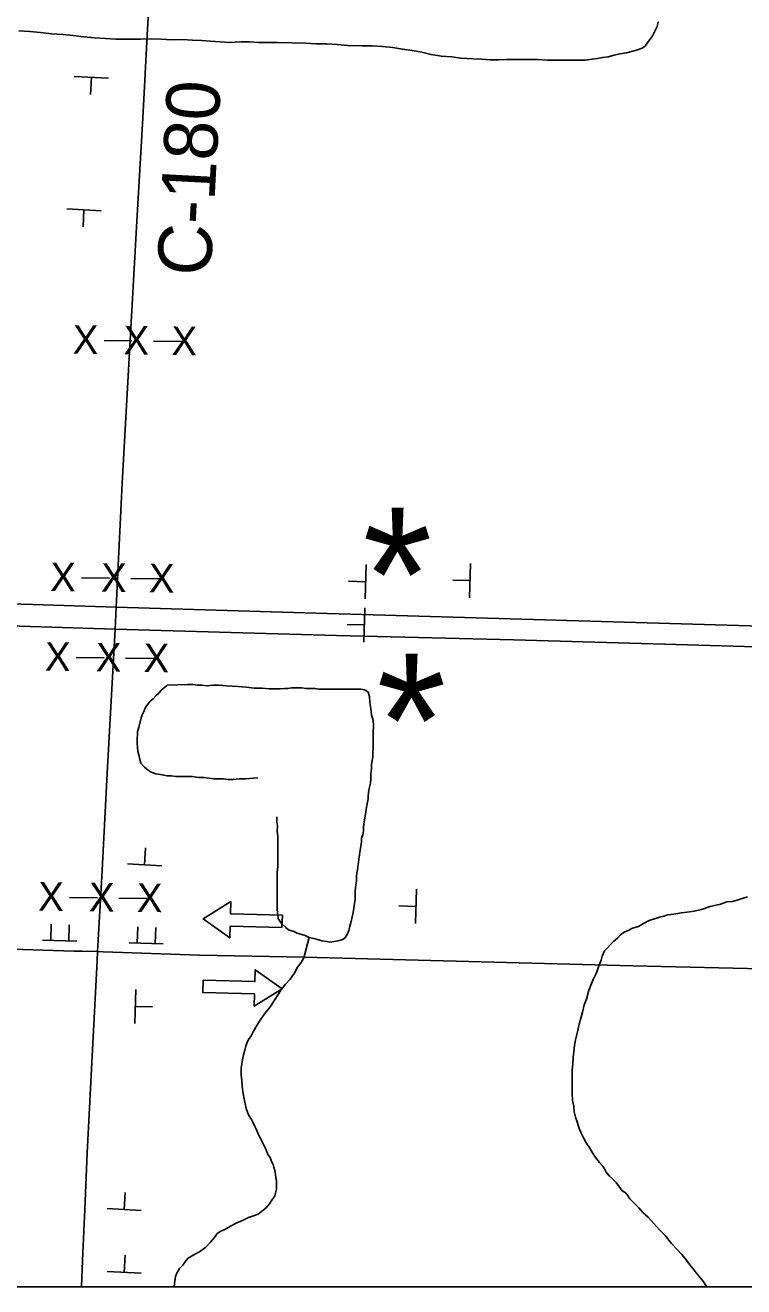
# Model space of a CAD drawing. Extents: x 1 to 1675, y -2 to 1113.
# Drawn here: x 1656.23 to 1659.58, y 1085.8 to 1091.69 of the extents above; entities that cross this region are included whole.
import ezdxf

# ---------------------------------------------------------------- set-up
doc = ezdxf.new("R2010")
doc.units = 0
for name, color, linetype in [('GM_X_County_Road_Text', 7, 'Continuous'), ('GM_X_State_Route', 7, 'Continuous'), ('SC_Scratch1', 7, 'Continuous'), ('SH_Data', 7, 'Continuous'), ('SH_Text', 7, 'Continuous'), ('SN_P_Signs', 7, 'Continuous'), ('SN_P_Text', 7, 'Continuous'), ('SN_X_Public', 7, 'Continuous')]:
    doc.layers.add(name, color=color, linetype=linetype)

msp = doc.modelspace()

# ---------------------------------------------------------------- linework, layer by layer
at = {"layer": 'GM_X_State_Route'}
for points in [[(1653.1763, 1089.0716), (1653.7087, 1089.0563), (1654.4064, 1089.0358), (1654.8887, 1089.0196), (1655.371, 1089.0075), (1656.2656, 1088.9829), (1656.6538, 1088.9713), (1657.5335, 1088.9451), (1659.6102, 1088.8844), (1660.288, 1088.8659), (1660.8126, 1088.8494), (1661.4466, 1088.8312), (1662.4959, 1088.8007), (1663.3048, 1088.777), (1663.7714, 1088.7638), (1663.8294, 1088.7624), (1664.6819, 1088.737), (1665.1629, 1088.7239), (1665.8187, 1088.7038), (1666.2558, 1088.6901), (1667.4561, 1088.6514), (1667.5998, 1088.6492), (1667.8763, 1088.6439)], [(1653.1763, 1089.0716), (1653.7087, 1089.0563), (1654.4064, 1089.0358), (1654.8887, 1089.0196), (1655.371, 1089.0075), (1656.2656, 1088.9829), (1656.6538, 1088.9713), (1657.5335, 1088.9451), (1659.6102, 1088.8844)], [(1653.1763, 1088.972), (1654.1058, 1088.9448), (1655.1549, 1088.9137), (1655.8542, 1088.8935), (1656.6489, 1088.8688), (1657.2445, 1088.8506), (1657.6825, 1088.8393), (1658.51, 1088.8187), (1659.3192, 1088.7948), (1660.9157, 1088.748), (1661.55, 1088.7295), (1662.0093, 1088.7178), (1663.1466, 1088.6833), (1663.7686, 1088.6652), (1664.4369, 1088.6454), (1665.8366, 1088.6041), (1666.8645, 1088.5732), (1667.7577, 1088.5488), (1667.8763, 1088.5445)], [(1653.1763, 1088.972), (1654.1058, 1088.9448), (1655.1549, 1088.9137), (1655.8542, 1088.8935), (1656.6489, 1088.8688), (1657.2445, 1088.8506), (1657.6825, 1088.8393), (1658.51, 1088.8187), (1659.3192, 1088.7948), (1660.9157, 1088.748), (1661.55, 1088.7295), (1662.0093, 1088.7178), (1663.1466, 1088.6833), (1663.7686, 1088.6652), (1664.4369, 1088.6454), (1665.8366, 1088.6041), (1666.8645, 1088.5732), (1667.7577, 1088.5488), (1668.0608, 1088.5378), (1669.2047, 1088.5077), (1669.5547, 1088.5002), (1670.1889, 1088.4798), (1670.4622, 1088.472)]]:
    msp.add_lwpolyline(points, dxfattribs=at)
at = {"layer": 'SC_Scratch1'}
for points in [[(1659.1832, 1091.7008), (1659.1778, 1091.6794), (1659.1671, 1091.658), (1659.1563, 1091.6367), (1659.1456, 1091.6206), (1659.1349, 1091.6073), (1659.1214, 1091.5886), (1659.108, 1091.5779), (1659.0813, 1091.57), (1659.0652, 1091.5647), (1659.0357, 1091.5568), (1659.0036, 1091.5515), (1658.9769, 1091.5463), (1658.9501, 1091.5383), (1658.9233, 1091.5357), (1658.8992, 1091.5305), (1658.8751, 1091.5279), (1658.843, 1091.5226), (1658.8082, 1091.5227), (1658.752, 1091.5229), (1658.7092, 1091.5231), (1658.6664, 1091.5232), (1658.6209, 1091.526), (1658.5835, 1091.5261), (1658.546, 1091.5262), (1658.5112, 1091.5263), (1658.4738, 1091.5265), (1658.439, 1091.5239), (1658.3988, 1091.524), (1658.3587, 1091.5268), (1658.3186, 1091.5296)], [(1658.3186, 1091.5296), (1658.2624, 1091.5325), (1658.2196, 1091.538), (1658.1714, 1091.5408), (1658.1233, 1091.549), (1658.0805, 1091.5598), (1658.035, 1091.568), (1657.9896, 1091.5735), (1657.9441, 1091.5817), (1657.8959, 1091.5872), (1657.8478, 1091.59), (1657.7996, 1091.5901), (1657.7354, 1091.5904), (1657.6846, 1091.5959), (1657.6364, 1091.5987), (1657.5856, 1091.5989), (1657.5374, 1091.6017), (1657.4063, 1091.6048), (1657.3635, 1091.6049), (1657.318, 1091.6051), (1657.2779, 1091.6079), (1657.2377, 1091.608), (1657.1815, 1091.6055), (1657.1387, 1091.6083), (1657.0933, 1091.6111), (1657.0531, 1091.6139), (1657.0103, 1091.6167), (1656.9622, 1091.6196), (1656.9113, 1091.6171), (1656.8632, 1091.6199), (1656.8177, 1091.6227), (1656.7695, 1091.6202), (1656.7187, 1091.6203), (1656.6518, 1091.6206), (1656.6036, 1091.6234), (1656.5528, 1091.6262), (1656.502, 1091.6317), (1656.4538, 1091.6372), (1656.4057, 1091.6428), (1656.3521, 1091.6456), (1656.3013, 1091.6511), (1656.2505, 1091.6566), (1656.1997, 1091.6595)], [(1656.8922, 1088.6067), (1656.8884, 1088.6046), (1656.8642, 1088.5832), (1656.8535, 1088.5699), (1656.8401, 1088.5592), (1656.8267, 1088.5432), (1656.8133, 1088.5326), (1656.7918, 1088.5059), (1656.7811, 1088.4818), (1656.7757, 1088.4685), (1656.7703, 1088.4551), (1656.7595, 1088.4097), (1656.7541, 1088.391), (1656.7541, 1088.3776), (1656.7513, 1088.3589), (1656.7513, 1088.3375), (1656.7539, 1088.3134), (1656.7565, 1088.292), (1656.7619, 1088.2759), (1656.7645, 1088.2598), (1656.7698, 1088.2437), (1656.7858, 1088.225), (1656.7992, 1088.2142), (1656.8179, 1088.2008), (1656.8393, 1088.1927), (1656.8607, 1088.19), (1656.8767, 1088.1872), (1656.8901, 1088.1845), (1656.9115, 1088.1845), (1656.9329, 1088.1817), (1656.957, 1088.1816), (1656.9811, 1088.1815), (1657.0078, 1088.1815), (1657.0399, 1088.176), (1657.0667, 1088.1759), (1657.0881, 1088.1732), (1657.1095, 1088.1704), (1657.1335, 1088.1704), (1657.155, 1088.1703), (1657.1763, 1088.1675), (1657.2004, 1088.1675), (1657.2272, 1088.1701), (1657.2593, 1088.1699), (1657.2941, 1088.1725), (1657.3151, 1088.174)], [(1657.7071, 1087.4194), (1657.7205, 1087.4274), (1657.7313, 1087.4434), (1657.7393, 1087.4621), (1657.7447, 1087.4835), (1657.7501, 1087.5049), (1657.7555, 1087.5263), (1657.7582, 1087.5396), (1657.7609, 1087.5557), (1657.7664, 1087.5878), (1657.7691, 1087.6092), (1657.7691, 1087.6279), (1657.7692, 1087.6493), (1657.7719, 1087.6734), (1657.7746, 1087.6948), (1657.7747, 1087.7135), (1657.7774, 1087.7322), (1657.7801, 1087.7456), (1657.7828, 1087.7697), (1657.791, 1087.8285), (1657.7937, 1087.8472), (1657.7964, 1087.8632), (1657.7991, 1087.8793), (1657.7992, 1087.8927), (1657.8045, 1087.9087), (1657.8073, 1087.9274), (1657.8073, 1087.9435), (1657.81, 1087.9595), (1657.8127, 1087.9782), (1657.8181, 1088.005), (1657.8209, 1088.0264), (1657.8236, 1088.0451), (1657.8263, 1088.0611), (1657.829, 1088.0772), (1657.8291, 1088.0906), (1657.8318, 1088.1066), (1657.8345, 1088.1253), (1657.8399, 1088.1494), (1657.8426, 1088.1708), (1657.8427, 1088.1922), (1657.8454, 1088.2162), (1657.8454, 1088.2377), (1657.8482, 1088.2537), (1657.8509, 1088.2724), (1657.8509, 1088.2938), (1657.8537, 1088.3152), (1657.8537, 1088.3366), (1657.8537, 1088.3553), (1657.8538, 1088.3741), (1657.8538, 1088.3928), (1657.8539, 1088.4089), (1657.8539, 1088.4249), (1657.8513, 1088.449), (1657.846, 1088.4677), (1657.8433, 1088.4865), (1657.8407, 1088.5079), (1657.8381, 1088.5266), (1657.8355, 1088.5534), (1657.8302, 1088.5748), (1657.8141, 1088.5856), (1657.7954, 1088.5883), (1657.774, 1088.5884), (1657.7606, 1088.5884), (1657.7446, 1088.5885), (1657.7205, 1088.5885), (1657.7044, 1088.5886), (1657.6911, 1088.5886), (1657.675, 1088.5887), (1657.6616, 1088.5887), (1657.6482, 1088.5888), (1657.6322, 1088.5888), (1657.6161, 1088.5889), (1657.6001, 1088.5889), (1657.5813, 1088.5917), (1657.5626, 1088.5917), (1657.5412, 1088.5918), (1657.5198, 1088.5945), (1657.4904, 1088.5946), (1657.4717, 1088.5947), (1657.4556, 1088.5921), (1657.4395, 1088.5921), (1657.4208, 1088.5895), (1657.3967, 1088.5896), (1657.3673, 1088.5897), (1657.3352, 1088.5924), (1657.2977, 1088.5925), (1657.2603, 1088.598), (1657.2228, 1088.6008), (1657.1693, 1088.6037), (1657.1345, 1088.6065), (1657.1051, 1088.6065), (1657.0783, 1088.604), (1657.0543, 1088.6067), (1657.0329, 1088.6068), (1657.0115, 1088.6095), (1656.9874, 1088.6096), (1656.8922, 1088.6067)], [(1657.4034, 1087.9934), (1657.4034, 1087.9822), (1657.4033, 1087.9688), (1657.406, 1087.9501), (1657.4059, 1087.926), (1657.4085, 1087.9019), (1657.4085, 1087.8779), (1657.4084, 1087.8591), (1657.4084, 1087.8431), (1657.4083, 1087.8217), (1657.4083, 1087.8029), (1657.4083, 1087.7842), (1657.4082, 1087.7601), (1657.4055, 1087.7361), (1657.4054, 1087.712), (1657.4054, 1087.6879), (1657.4053, 1087.6692), (1657.4053, 1087.6505), (1657.4052, 1087.6291), (1657.4052, 1087.613), (1657.4051, 1087.5969), (1657.4051, 1087.5782), (1657.4051, 1087.5595), (1657.4077, 1087.5354), (1657.4103, 1087.5193), (1657.4183, 1087.5059), (1657.429, 1087.4925), (1657.445, 1087.4764), (1657.4584, 1087.4657), (1657.4824, 1087.4576), (1657.4985, 1087.4495), (1657.5199, 1087.4441), (1657.5359, 1087.4387), (1657.5546, 1087.4306), (1657.576, 1087.4252), (1657.6001, 1087.4197), (1657.6135, 1087.4143), (1657.6375, 1087.4116), (1657.6509, 1087.4089), (1657.6696, 1087.4115), (1657.6884, 1087.4141), (1657.7071, 1087.4194)], [(1659.5993, 1087.6194), (1659.5752, 1087.6114), (1659.5511, 1087.6035), (1659.5297, 1087.5982), (1659.5029, 1087.5956), (1659.4735, 1087.585), (1659.4253, 1087.5745), (1659.3851, 1087.5612), (1659.3503, 1087.5533), (1659.3182, 1087.548), (1659.2914, 1087.5455), (1659.2647, 1087.5402), (1659.2433, 1087.5376), (1659.2272, 1087.5349), (1659.2085, 1087.5297), (1659.1897, 1087.5244), (1659.171, 1087.5191), (1659.1415, 1087.5085), (1659.1147, 1087.4952), (1659.0906, 1087.4819), (1659.0638, 1087.4739), (1659.0424, 1087.4633), (1659.0237, 1087.4553), (1659.0076, 1087.442), (1658.9942, 1087.4287), (1658.9754, 1087.4127), (1658.9325, 1087.3673), (1658.9217, 1087.3433), (1658.9163, 1087.3246), (1658.9056, 1087.2979), (1658.8948, 1087.2658), (1658.8813, 1087.2364), (1658.8679, 1087.207), (1658.8571, 1087.1776), (1658.849, 1087.1429), (1658.8383, 1087.1161), (1658.8301, 1087.0814), (1658.814, 1087.0253), (1658.8059, 1086.9905), (1658.7977, 1086.9531), (1658.7923, 1086.9263), (1658.7896, 1086.8969), (1658.7868, 1086.8702), (1658.7841, 1086.8407), (1658.7814, 1086.8113), (1658.7813, 1086.7739), (1658.7812, 1086.7391), (1658.7811, 1086.7043), (1658.7837, 1086.6695), (1658.789, 1086.6427), (1658.7916, 1086.616), (1658.7969, 1086.5919), (1658.8049, 1086.5705), (1658.8129, 1086.5437), (1658.8235, 1086.5169), (1658.8341, 1086.4955), (1658.8475, 1086.4713), (1658.8635, 1086.4472), (1658.8768, 1086.4257), (1658.8901, 1086.4043), (1658.9088, 1086.3802), (1658.9222, 1086.3667), (1658.9302, 1086.3533), (1658.9408, 1086.3346), (1658.9542, 1086.3185)], [(1657.5546, 1087.4306), (1657.5303, 1087.3344), (1657.5169, 1087.313), (1657.5008, 1087.2916), (1657.4847, 1087.2623), (1657.4659, 1087.2356), (1657.4444, 1087.2116), (1657.4229, 1087.1849), (1657.4095, 1087.1635), (1657.3934, 1087.1368), (1657.3746, 1087.1074), (1657.3478, 1087.0754), (1657.329, 1087.0487), (1657.3102, 1087.0193), (1657.2941, 1086.9926), (1657.2833, 1086.9713), (1657.2726, 1086.9553), (1657.2645, 1086.9419), (1657.2591, 1086.9232), (1657.2537, 1086.9045), (1657.2483, 1086.8831), (1657.2429, 1086.859), (1657.2402, 1086.8403), (1657.2375, 1086.8216), (1657.2374, 1086.8055), (1657.2374, 1086.7868), (1657.24, 1086.7627), (1657.2426, 1086.736), (1657.2453, 1086.7092), (1657.2505, 1086.6771), (1657.2611, 1086.6316), (1657.2718, 1086.6021), (1657.2851, 1086.5807), (1657.2931, 1086.5646), (1657.3011, 1086.5485), (1657.3091, 1086.5324), (1657.3171, 1086.5137), (1657.3277, 1086.4922), (1657.3384, 1086.4708), (1657.3463, 1086.4547), (1657.3543, 1086.4386), (1657.3623, 1086.4172), (1657.373, 1086.4038), (1657.3783, 1086.3851), (1657.3863, 1086.3716), (1657.3889, 1086.3583), (1657.3943, 1086.3422), (1657.4022, 1086.2913), (1657.4021, 1086.2753), (1657.4021, 1086.2565), (1657.3967, 1086.2379), (1657.394, 1086.2245), (1657.3779, 1086.2005), (1657.3698, 1086.1871), (1657.3537, 1086.1684), (1657.3403, 1086.1578), (1657.3162, 1086.1391), (1657.2948, 1086.1312), (1657.2707, 1086.1232), (1657.2439, 1086.1099), (1657.2171, 1086.0993), (1657.1876, 1086.0833), (1657.1608, 1086.0674), (1657.1421, 1086.0594), (1657.126, 1086.0487), (1657.1126, 1086.0301), (1657.0938, 1086.0087), (1657.0723, 1085.9847), (1657.0429, 1085.9634), (1657.0268, 1085.9554), (1657.0134, 1085.9474), (1656.9893, 1085.9341), (1656.9785, 1085.9208), (1656.9651, 1085.9021), (1656.949, 1085.8861), (1656.9383, 1085.8674), (1656.9302, 1085.8487), (1656.9275, 1085.8273), (1656.9248, 1085.8033), (1656.9248, 1085.8005)], [(1658.9542, 1086.3185), (1658.9675, 1086.3051), (1658.9862, 1086.2863), (1658.9995, 1086.2702), (1659.0155, 1086.2487), (1659.0289, 1086.2407), (1659.0396, 1086.2273), (1659.0502, 1086.2112), (1659.0929, 1086.1682), (1659.1116, 1086.1468), (1659.1357, 1086.1253), (1659.1624, 1086.0958), (1659.189, 1086.0663), (1659.2157, 1086.0394), (1659.2451, 1086.0019), (1659.2718, 1085.975), (1659.2931, 1085.9509), (1659.3145, 1085.924), (1659.3305, 1085.9026), (1659.3465, 1085.8838), (1659.3598, 1085.865), (1659.3758, 1085.8463), (1659.3919, 1085.8275), (1659.4052, 1085.806), (1659.41, 1085.8005)]]:
    msp.add_lwpolyline(points, dxfattribs=at)
at = {"layer": 'SH_Data'}
msp.add_lwpolyline([(1653.1763, 1105.4005), (1672.2022, 1105.4005), (1672.2022, 1085.8005), (1653.1763, 1085.8005)], close=True, dxfattribs=at)
at = {"layer": 'SH_Text'}
for p, q in [((1657.0592, 1087.5165), (1657.189, 1087.5976)), ((1657.189, 1087.5976), (1657.1874, 1087.5406)), ((1657.0592, 1087.5165), (1657.1842, 1087.4281)), ((1657.1874, 1087.5406), (1657.4293, 1087.5337)), ((1657.4293, 1087.5337), (1657.4277, 1087.4758)), ((1657.1842, 1087.4281), (1657.1858, 1087.4826)), ((1657.1858, 1087.4826), (1657.4277, 1087.4758)), ((1657.3031, 1087.2791), (1657.3016, 1087.2245)), ((1657.4282, 1087.1907), (1657.3031, 1087.2791)), ((1657.058, 1087.1734), (1657.0596, 1087.2314)), ((1657.3016, 1087.2245), (1657.0596, 1087.2314)), ((1657.2999, 1087.1665), (1657.058, 1087.1734)), ((1657.4282, 1087.1907), (1657.2983, 1087.1095)), ((1657.2983, 1087.1095), (1657.2999, 1087.1665))]:
    msp.add_line(p, q, dxfattribs=at)
for points in [[(1657.4277, 1087.4758), (1657.1858, 1087.4826), (1657.1842, 1087.4281), (1657.0592, 1087.5165), (1657.189, 1087.5976), (1657.1874, 1087.5406), (1657.4293, 1087.5337)], [(1657.0597, 1087.2314), (1657.3016, 1087.2245), (1657.3031, 1087.2791), (1657.4282, 1087.1907), (1657.2983, 1087.1095), (1657.2999, 1087.1665), (1657.058, 1087.1734)]]:
    msp.add_lwpolyline(points, close=True, dxfattribs=at)
msp.add_lwpolyline([(1656.5672, 1087.3642), (1656.5934, 1087.3633), (1657.0425, 1087.3482), (1657.533, 1087.3387), (1659.0643, 1087.2977), (1660.2675, 1087.2696), (1661.405, 1087.2377), (1662.6955, 1087.1976), (1663.5705, 1087.1736), (1663.7236, 1087.1696)], dxfattribs=at)
at = {"layer": 'SN_P_Signs'}
for p, q in [((1656.6184, 1091.4383), (1656.4586, 1091.4466)), ((1656.5385, 1091.4425), (1656.5344, 1091.3626)), ((1656.5835, 1090.8203), (1656.4237, 1090.8286)), ((1656.5036, 1090.8244), (1656.4995, 1090.7445)), ((1656.5973, 1090.2149), (1656.7275, 1090.2132)), ((1656.8276, 1090.2119), (1656.9645, 1090.2101)), ((1658.3019, 1089.0149), (1658.3066, 1089.1748)), ((1656.4922, 1089.1078), (1656.6224, 1089.1061)), ((1656.7225, 1089.1047), (1656.8593, 1089.103)), ((1658.3042, 1089.0948), (1658.2243, 1089.0972)), ((1656.4677, 1088.736), (1656.5978, 1088.7343)), ((1656.6979, 1088.733), (1656.8348, 1088.7312)), ((1656.7869, 1087.7688), (1656.791, 1087.8487)), ((1656.707, 1087.773), (1656.8668, 1087.7647)), ((1658.0508, 1087.4948), (1658.0556, 1087.6547)), ((1656.4362, 1087.6171), (1656.5664, 1087.6154)), ((1656.6665, 1087.6141), (1656.8033, 1087.6123)), ((1658.0532, 1087.5748), (1657.9732, 1087.5771)), ((1656.3487, 1087.4163), (1656.3512, 1087.4916)), ((1656.433, 1087.4136), (1656.4354, 1087.4889)), ((1656.7524, 1087.404), (1656.7548, 1087.4792)), ((1656.8367, 1087.4013), (1656.8391, 1087.4765)), ((1656.4699, 1087.4124), (1656.3103, 1087.4175)), ((1656.8736, 1087.4001), (1656.714, 1087.4052)), ((1656.7459, 1087.188), (1656.7411, 1087.0281)), ((1656.7435, 1087.1081), (1656.8235, 1087.1057)), ((1656.6913, 1086.1609), (1656.6954, 1086.2407)), ((1656.6114, 1086.165), (1656.7712, 1086.1567)), ((1656.6913, 1085.8676), (1656.6954, 1085.9475)), ((1656.6114, 1085.8717), (1656.7712, 1085.8635))]:
    msp.add_line(p, q, dxfattribs=at)
for points in [[(1656.6538, 1088.9713), (1656.6824, 1089.549), (1656.7502, 1090.7723), (1656.779, 1091.2527), (1656.8004, 1091.6678), (1656.8346, 1092.2577), (1656.8383, 1092.3049), (1656.8451, 1092.3768), (1656.8483, 1092.4109)], [(1656.6538, 1088.9713), (1656.6824, 1089.549), (1656.7502, 1090.7723), (1656.779, 1091.2527), (1656.8004, 1091.6678), (1656.8346, 1092.2577), (1656.8383, 1092.3049), (1656.8451, 1092.3768), (1656.8483, 1092.4109)], [(1656.6489, 1088.8688), (1656.6538, 1088.9713)], [(1656.6489, 1088.8688), (1656.6538, 1088.9713)], [(1656.5672, 1087.3642), (1656.5873, 1087.7139), (1656.6125, 1088.1945), (1656.6271, 1088.4787), (1656.6489, 1088.8688)], [(1656.5672, 1087.3642), (1656.5873, 1087.7139), (1656.6125, 1088.1945), (1656.6271, 1088.4787), (1656.6489, 1088.8688)], [(1653.1763, 1087.4595), (1653.5925, 1087.4528), (1654.5111, 1087.4263), (1655.2983, 1087.4042), (1656.4573, 1087.3668), (1656.495, 1087.3659), (1656.5672, 1087.3642)], [(1653.1763, 1087.4595), (1653.5925, 1087.4528), (1654.5111, 1087.4263), (1655.2983, 1087.4042), (1656.4573, 1087.3668), (1656.495, 1087.3659), (1656.5672, 1087.3642)], [(1656.5672, 1087.3642), (1656.5934, 1087.3633), (1657.0425, 1087.3482), (1657.533, 1087.3387), (1659.0643, 1087.2977), (1660.2675, 1087.2696), (1661.405, 1087.2377), (1662.6955, 1087.1976), (1663.5705, 1087.1736), (1663.7236, 1087.1696)], [(1656.5672, 1087.3642), (1656.5934, 1087.3633), (1657.0425, 1087.3482), (1657.533, 1087.3387), (1659.0643, 1087.2977), (1660.2675, 1087.2696), (1661.405, 1087.2377), (1662.6955, 1087.1976), (1663.5705, 1087.1736), (1663.7236, 1087.1696)]]:
    msp.add_lwpolyline(points, dxfattribs=at)
at = {"layer": 'SN_P_Text'}
msp.add_lwpolyline([(1656.4923, 1085.8005), (1656.4972, 1085.9224), (1656.5079, 1086.1627), (1656.5193, 1086.425), (1656.5429, 1086.9057), (1656.5646, 1087.3209), (1656.5672, 1087.3642)], dxfattribs=at)
msp.add_lwpolyline([(1656.4923, 1085.8005), (1656.4972, 1085.9224), (1656.5079, 1086.1627), (1656.5193, 1086.425), (1656.5429, 1086.9057), (1656.5646, 1087.3209), (1656.5672, 1087.3642)], dxfattribs=at)
at = {"layer": 'SN_X_Public'}
for p, q in [((1657.8156, 1089.0094), (1657.8203, 1089.1693)), ((1657.818, 1089.0893), (1657.738, 1089.0917)), ((1657.8098, 1088.8084), (1657.8144, 1088.9684)), ((1657.8121, 1088.8884), (1657.7321, 1088.8907))]:
    msp.add_line(p, q, dxfattribs=at)

# ---------------------------------------------------------------- texts
at = {"layer": 'GM_X_County_Road_Text'}
msp.add_text('C-180', height=0.25, rotation=86.97063, dxfattribs=at).set_placement((1657.0943, 1090.5122))
at = {"layer": 'SH_Text'}
for p in [(1657.8038, 1088.8108), (1657.8692, 1088.1298)]:
    msp.add_text('*', height=0.624, dxfattribs=at).set_placement(p)
at = {"layer": 'SN_P_Signs'}
for p in [(1656.4509, 1090.1533), (1656.6878, 1090.1502), (1656.9114, 1090.1472), (1656.3458, 1089.0461), (1656.5827, 1089.043), (1656.8063, 1089.0401), (1656.3212, 1088.6743), (1656.5582, 1088.6712), (1656.7818, 1088.6683), (1656.2898, 1087.5555), (1656.5267, 1087.5524), (1656.7503, 1087.5495)]:
    msp.add_text('X', height=0.1333, rotation=359.25135, dxfattribs=at).set_placement(p)

doc.saveas('drawing.dxf')
